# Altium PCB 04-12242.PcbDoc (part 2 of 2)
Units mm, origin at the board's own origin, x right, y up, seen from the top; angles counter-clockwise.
Board outline 90 x 78 mm, 2 copper layers (Top Layer, Bottom Layer), stack 1.57 mm thick; 64 components, 48 nets, 276 pads, 503 vias.
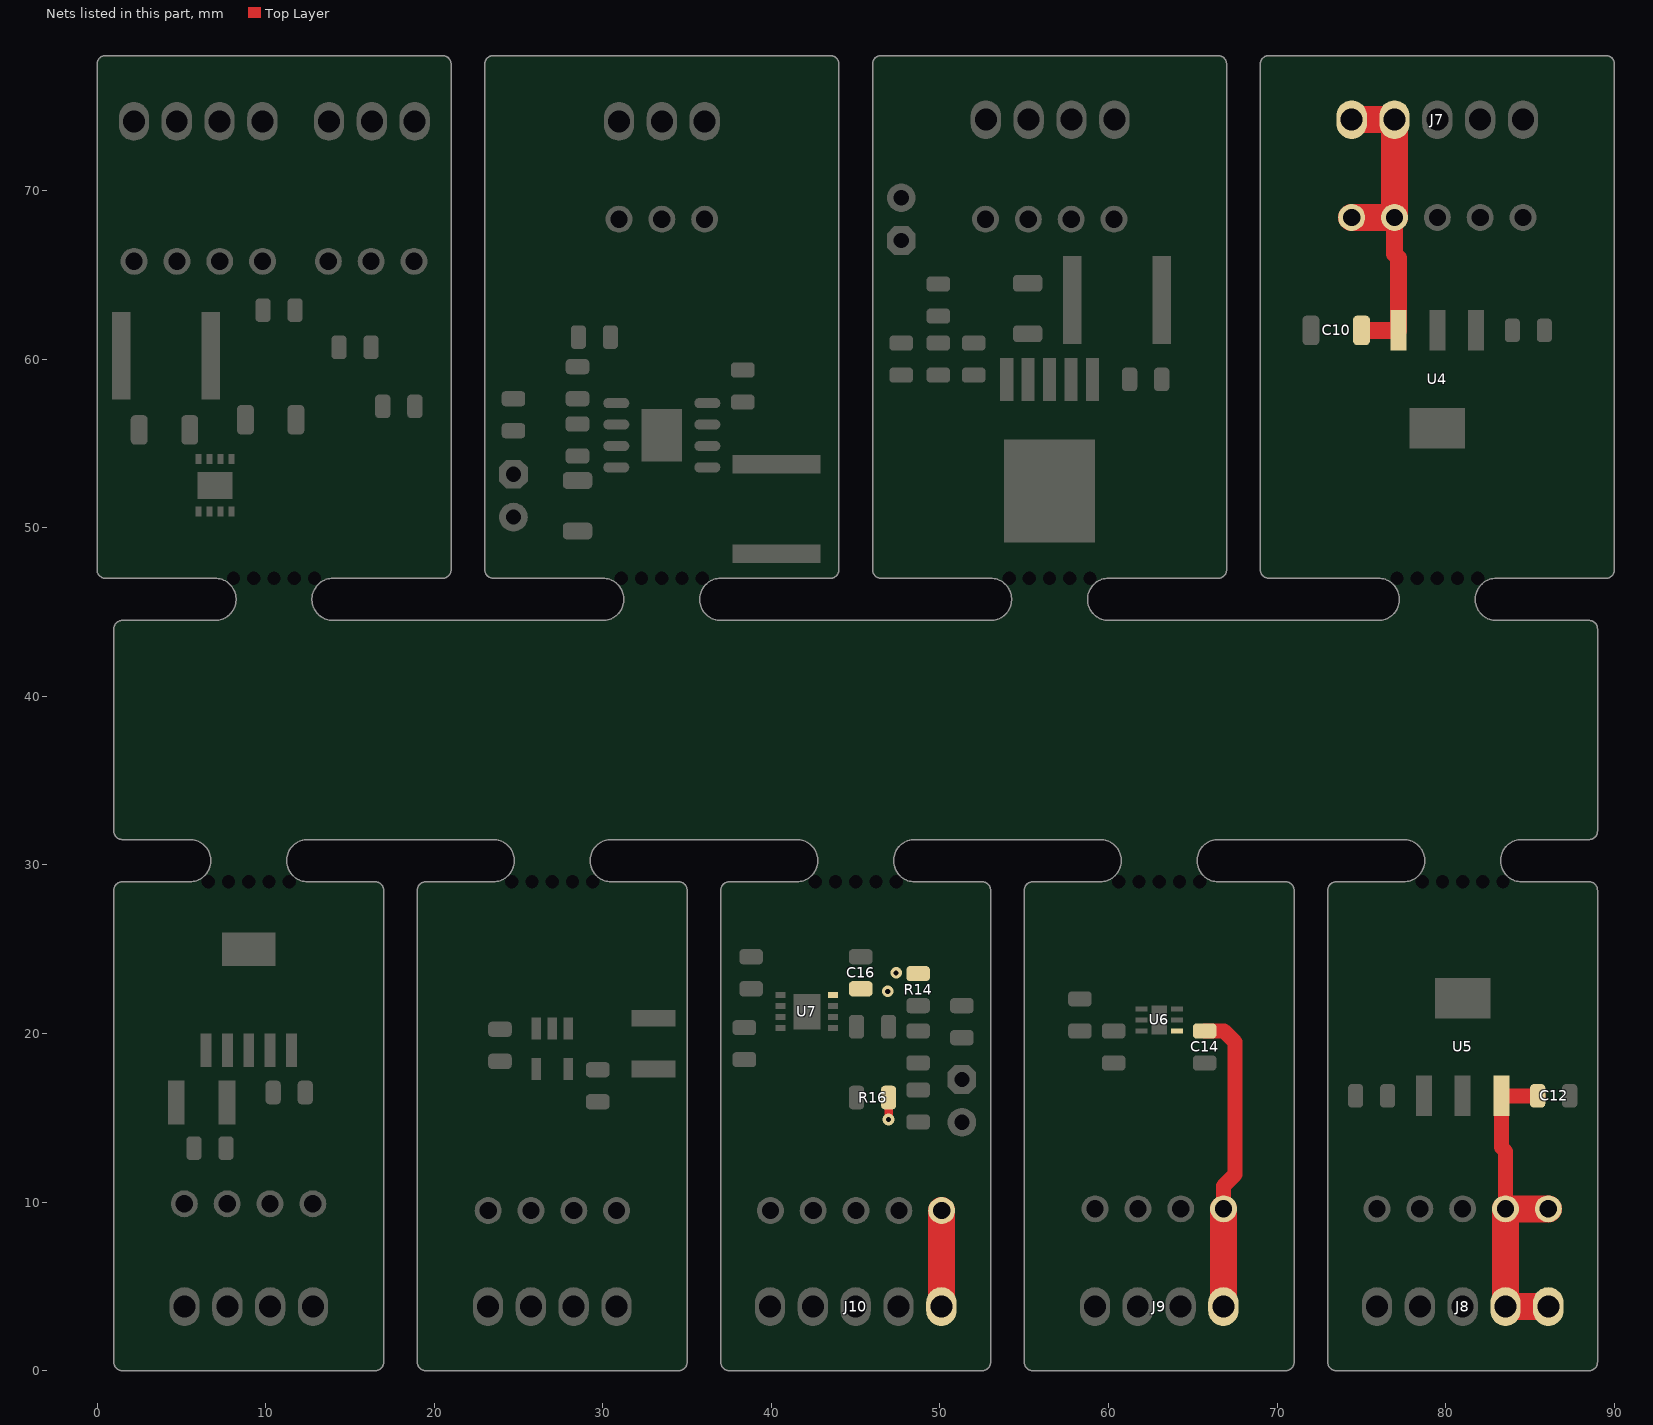
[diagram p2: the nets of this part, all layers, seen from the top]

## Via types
v1: diameter 0.7, hole 0.3, Top Layer to Bottom Layer, 503 vias

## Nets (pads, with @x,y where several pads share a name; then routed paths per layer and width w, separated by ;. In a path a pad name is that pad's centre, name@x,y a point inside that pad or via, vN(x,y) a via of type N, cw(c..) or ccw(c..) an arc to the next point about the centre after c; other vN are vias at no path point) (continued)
VOUT_6: C16.2 J10.5 pad.7@50.1,9.5 R14.2 R16.2 U7.8 | length 7
  Top Layer w0.5: v1(46.95,14.904) R16.2@46.95,16.2
  Top Layer w1.6: J10.5@50.08,3.8 50.1,3.82 pad.7@50.1,9.5
  other v1: 46.9,22.5 47.4,23.6
VOUT_7: C14.2 J9.4 pad.7@66.82,9.6 U6.4 | length 18.1
  Top Layer w0.9: C14.2@65.7,20.15 66.85,20.15 67.5,19.5 67.5,11.64 66.82,10.96 pad.7@66.82,9.6
  Top Layer w1.6: J9.4@66.81,3.8 66.81,9.59 pad.7@66.82,9.6
VOUT_8: C12.2 J8.4 J8.5 pad.7@83.54,9.6 pad.9@86.08,9.6 U5.3 | length 19.8
  Top Layer w0.9: pad.7@83.54,9.6 83.55,9.61 83.55,13 83.3,13.25 U5.3@83.3,16.3 C12.2@85.45,16.3
  Top Layer w1.6: J8.5@86.08,3.8 J8.4@83.54,3.8 pad.7@83.54,9.6 pad.9@86.08,9.6
VOUT_9: C10.2 J7.4 J7.5 pad.7@74.42,68.4 pad.7@76.96,68.4 U4.3 | length 19.9
  Top Layer w1: C10.2@75,61.7 U4.3@77.2,61.7 77.2,66 76.96,66.24 pad.7@76.96,68.4
  Top Layer w1.6: pad.7@74.42,68.4 pad.7@76.96,68.4 J7.4@76.96,74.2 J7.5@74.42,74.2
pads on no net: U1.6 U2.2 U2.3 U2.7 U6.5 U6.6 U8.4 U9.5

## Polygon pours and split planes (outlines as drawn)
VOUT1_1 on Top Layer "full" (solid, remove dead copper, pour order 49): 6.2,53.7 5.9,53.7 4.4,55.2 4.4,62 1.4,65 1.4,65.9 3,65.9 3,65.2 5.7,62.5 5.7,57.3 6.2,56.8
GND_9 on Top Layer "full" (solid, remove dead copper, pour order 102): 69.5,47.5 89.5,47.5 89.5,60 80.5,60 80.1,60.4 80.1,63.1 78.9,63.1 78.9,60.399 78.501,60 69.5,60
GND_8 on Top Layer "full" (solid, remove dead copper, pour order 103): 88.5,28.5 73.5,28.5 73.5,18 80,18 80.4,17.6 80.4,15 81.6,15 81.6,17.601 81.999,18 88.5,18
VOUT_5 on Top Layer "full" (solid, remove dead copper, pour order 41): 27.4,14 30.1,11.3 30.1,8.8 31.5,8.8 31.5,14.3 30.6,15.2 30.6,16.6 29.4,16.6 28.4,17.6 28.4,18.6 27.4,18.6 27.4,15.3
VOUT_3 on Top Layer "full" (solid, remove dead copper, pour order 98): 54.8,57.5 55.7,57.5 55.7,60.4 56.3,60.4 56.3,62.3 54.2,62.3 53.6,62.9 53.6,75.5 51.3,75.5 51.3,60.4 54.8,60.4
GND_3 on Top Layer "full" (solid, remove dead copper, pour order 96): 62.4,60.7 62.4,66.3 65.5,66.3 65.5,60.7
GND_1 on Top Layer "full" (solid, remove dead copper, pour order 94): 0.5,47.5 5.5,47.5 5.5,51.313 5.887,51.7 8.1,51.7 9.9,49.9 12.4,49.9 12.4,57.5 10.8,57.5 10.8,56 8.1,53.3 5.9,53.3 4,55.2 4,61.5 2.5,63 0.5,63 0.5,61.5
GND_2 on Top Layer "full" (solid, remove dead copper, pour order 60): 23.5,47.5 43.5,47.5 43.5,52.5 35.1,52.5 34.8,52.8 34.8,57.3 36,58.5 39.1,58.5 39.1,59.9 36.9,62.1 29.9,62.1 29.9,57 32.2,57 32.2,53 31,51.8 23.5,51.8
VOUT_2 on Top Layer "full" (solid, remove dead copper, pour order 57): 31.7,54.1 31.7,53.3 30.6,52.2 26.4,52.2 26.4,54.8 29.1,54.8 29.8,54.1
VIN_2 on Top Layer "full" (solid, remove dead copper, pour order 54): 35.3,54.2 35.3,52.9 43.5,52.9 43.5,62.1 36.9,68.7 35.1,68.7 35.1,65.5 39.5,61.1 39.5,56.6 37.1,54.2
ADJ_2 on Top Layer "full" (solid, remove dead copper, pour order 58): 31.7,56.6 31.7,55.6 27.7,55.6 27.7,58.2 29.3,58.2 29.3,57.2 29.9,56.6
GND_6 on Top Layer "full" (solid, remove dead copper, pour order 83): 40.1,16 44.2,16 44.2,18.4 42.9,19.7 42.9,22.5 44.3,23.9 46.2,23.9 47.3,25 52.5,25 52.5,28.5 37.5,28.5 37.5,23.9 39.9,23.9 41.3,22.5 41.3,20.6 40.1,20.6 40.1,18.4
VOUT_6 on Top Layer "full" (solid, remove dead copper, pour order 74): 43.3,22 43.3,22.5 44,23.2 44.1,23.3 46.3,23.3 47.2,24.2 49.6,24.2 49.6,22.9 48.2,22.9 47.3,22
NetC17_2 on Top Layer "full" (solid, remove dead copper, pour order 76): 43.3,21.2 45.6,21.2 45.6,19.6 44.7,19.6 44.5,19.8 44.5,20.5 44.3,20.7 43.3,20.7
VIN_6 on Top Layer "full" (solid, remove dead copper, pour order 73): 37.5,19.8 39.3,19.8 39.3,21.4 40.9,21.4 40.9,22.5 39.7,22.5 39.7,23.5 37.5,23.5
GND_7 on Top Layer "full" (solid, remove dead copper, pour order 69): 59.5,15 66.5,15 66.5,18.9 64.4,18.9 63.4,19.9 63.4,21.7 64.5,22.8 70.5,22.8 70.5,28.5 55.5,28.5 55.5,22.8 61.5,22.8 62.6,21.7 62.6,19.9 61.6,18.9 59.5,18.9
VOUT_7 on Top Layer "full" (solid, remove dead copper, pour order 67): 63.7,19.9 63.7,20.4 64.6,20.4 64.9,20.7 66.5,20.7 66.5,19.6 64.9,19.6 64.6,19.9
VIN_7 on Top Layer "full" (solid, remove dead copper, pour order 64): 62.3,20.4 62.3,19.9 61.4,19.9 61.1,19.6 57.5,19.6 57.5,20.7 61.1,20.7 61.4,20.4
VOUT2_1 on Top Layer "full" (solid, remove dead copper, pour order 53): 7.8,53.7 8.1,53.7 9.6,55.2 9.6,57.5 8.1,57.5 7.3,56.7 7.3,55 7.8,54.5
VIN_1 on Top Layer "full" (solid, remove dead copper, pour order 42): 6.9,53.7 6.5,53.7 6.5,56.913 6.1,57.313 6.1,62.9 7.4,62.9 7.4,57.413 6.9,56.913
GND_5 on Top Layer "full" (solid, remove dead copper, pour order 37): 30.6,21.5 31.7,20.4 34.5,20.4 34.5,28.5 19.5,28.5 19.5,21.5 26.5,21.5 26.7,21.3 26.7,19.6 27.3,19.6 27.3,21.3 27.5,21.5
VIN_5 on Top Layer "full" (solid, remove dead copper, pour order 30): 31.5,16 34.5,16 34.5,19.6 31.9,19.6 30.5,21 27.6,21 27.6,19.6 30.2,19.6 31.5,18.3
GND_4 on Top Layer "full" (solid, remove dead copper, pour order 27): 11.9,15.5 16.5,15.5 16.5,28.5 1.5,28.5 1.5,14.4 5.3,14.4 5.3,20.6 5.7,21 7.9,21 8.6,20.3 8.6,18 9.4,18 9.4,20.3 10.1,21 12,21 12.5,20.5 12.5,18 11.9,17.4
VOUT_4 on Top Layer "full" (solid, remove dead copper, pour order 23): 10.7,20 9.8,20 9.8,13.7 12,11.5 12,9.8 13.6,9.8 13.6,11.9 11,14.5 11,17.3 10.7,17.6
VIN_4 on Top Layer "full" (solid, remove dead copper, pour order 14): 8.1,20 7.3,20 7.3,17.6 6.9,17.2 6.9,9.8 8.5,9.8 8.5,17.2 8.1,17.6
GND_3 on Top Layer "full" (solid, remove dead copper, pour order 4): 46.5,56.8 66.5,56.8 66.5,47.5 46.5,47.5
VIN_3 on Top Layer "full" (solid, remove dead copper, pour order 13): 58.3,57.5 57.3,57.5 57.3,60.5 57,60.8 57,68.3 58.6,68.3 58.6,60.8 58.3,60.5
GND_1 on Bottom Layer "full" (solid, remove dead copper, pour order 12): 0.5,47.5 20.5,47.5 20.5,77.5 0.5,77.5
GND_8 on Bottom Layer "full" (solid, remove dead copper, pour order 79): 73.5,28.5 88.5,28.5 88.5,0.5 73.5,0.5
GND_9 on Bottom Layer "full" (solid, remove dead copper, pour order 35): 69.5,47.5 89.5,47.5 89.5,77.5 69.5,77.5
GND_5 on Bottom Layer "full" (solid, remove dead copper, pour order 51): 19.5,28.5 34.5,28.5 34.5,0.5 19.5,0.5
GND_2 on Bottom Layer "full" (solid, remove dead copper, pour order 81): 23.5,47.5 43.5,47.5 43.5,77.5 23.5,77.5
VIN_6 on Bottom Layer "full" (solid, remove dead copper, pour order 7): 45.8,9.4 44.2,9.4 44.2,10.5 37.5,17.2 37.5,22 39.5,22 39.5,17.3 45.8,11
VOUT_6 on Bottom Layer "full" (solid, remove dead copper, pour order 8): 46.4,13.9 49.3,11 49.3,9.5 50.9,9.5 50.9,11.4 47.9,14.4 47.9,24.1 46.4,24.1 46.4,15.8
GND_6 on Bottom Layer "full" (solid, remove dead copper, pour order 59): 37.5,28.5 52.5,28.5 52.5,0.5 37.5,0.5
GND_7 on Bottom Layer "full" (solid, remove dead copper, pour order 77): 55.5,28.5 70.5,28.5 70.5,0.5 55.5,0.5
VOUT_2 on Bottom Layer "full" (solid, remove dead copper, pour order 9): 28.3,52.2 26.4,52.2 26.4,59.1 30,62.7 30,69.3 31.9,69.3 31.9,62.1 28.3,58.5
VOUT2_1 on Bottom Layer "full" (solid, remove dead copper, pour order 6): 9.1,54.8 7.3,54.8 7.3,61.5 3.9,64.9 3.9,65.8 5.6,65.8 5.6,65 9.1,61.5
VIN_5 on Bottom Layer "full" (solid, remove dead copper, pour order 10): 26.5,8.8 25,8.8 25,10.2 31.8,17 34.5,17 34.5,15.5 32.5,15.5 26.5,9.5
GND_4 on Bottom Layer "full" (solid, remove dead copper, pour order 50): 1.5,28.5 16.5,28.5 16.5,0.5 1.5,0.5
GND_3 on Bottom Layer "full" (solid, remove dead copper, pour order 11): 46.5,47.5 66.5,47.5 66.5,77.5 46.5,77.5

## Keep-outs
Keep-Out Layer:
  text "'.Layer_Name'" at 297.5,-121.069 h1.5

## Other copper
Top Layer:
  text "'.ProjectPCBFabRevision'" at 332.678,-120.891 h1.5
  text "'.Layer_Name'" at 297.5,-121.069 h1.5
Bottom Layer:
  text "'.ProjectPCBFabNumber'-R'.ProjectPCBFabRevision'" at 2.5,32.673 h1 r270
  text ".ProjectPCBFabRevision" at 332.678,-120.891 h1.5
  text "'.Layer_Name'" at 297.5,-121.069 h1.5

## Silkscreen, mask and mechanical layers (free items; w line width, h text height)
Top Overlay:
  region: 19 vertices and 2 holes, not listed, extent 74.168,34.34 81.91,42.072
  text "VOUT" at 31.778,70.384 h1.2 r180
  text "GND" at 34.639,70.384 h1.2 r180
  text "VIN" at 37.05,70.384 h1.2 r180
  text "VOUT" at 53.678,70.284 h1.2 r180
  text "GND" at 56.439,70.284 h1.2 r180
  text "VIN" at 58.75,70.284 h1.2 r180
  text "EN" at 61.062,70.284 h1.2 r180
  text "VOUT" at 77.178,70.284 h1.2 r180
  text "GND" at 80.639,70.284 h1.2 r180
  text "VIN" at 84.15,70.284 h1.2 r180
  text "EN" at 14.244,68.038 h1.2 r90
  text "VIN" at 10.304,67.85 h1.2 r90
  text "GND" at 7.764,67.561 h1.2 r90
  text "PWG1" at 19.184,67.249 h1.2 r90
  text "PWG2" at 16.684,67.188 h1.2 r90
  text "VOUT1" at 2.584,66.97 h1.2 r90
  text "VOUT2" at 5.084,66.84 h1.2 r90
  text "'.ProjectPartNumber'" at 40.6,39.6 h2
  text "Building Block Solutions - Automotive LDOs" at 29.5,35.1 h2
  text "M" at 5,34 h8
  text "EN" at 4.438,7.716 h1.2
  text "VIN" at 6.75,7.716 h1.2
  text "GND" at 9.061,7.716 h1.2
  text "VOUT" at 11.822,7.716 h1.2
  text "EN" at 58.458,7.616 h1.2
  text "VIN" at 60.77,7.616 h1.2
  text "GND" at 63.081,7.616 h1.2
  text "VOUT" at 65.842,7.616 h1.2
  text "VIN" at 76.35,7.616 h1.2
  text "GND" at 79.761,7.616 h1.2
  text "VOUT" at 83.322,7.616 h1.2
  text "EN" at 22.458,7.516 h1.2
  text "VIN" at 24.77,7.516 h1.2
  text "GND" at 27.081,7.516 h1.2
  text "VOUT" at 29.842,7.516 h1.2
  text "PWG" at 38.632,7.516 h1.2
  text "EN" at 41.758,7.516 h1.2
  text "VIN" at 44.07,7.516 h1.2
  text "GND" at 46.381,7.516 h1.2
  text "VOUT" at 49.142,7.516 h1.2
  text "'.ProjectPCBFabRevision'" at 332.678,-120.891 h1.5
  text "'.Layer_Name'" at 297.5,-121.069 h1.5
Bottom Overlay:
  drawing of 9 lines, arcs and shapes, not listed
  text "Dual Output High Voltage LDO" at 2.263,72.054 h1.3 r180
  text "High Voltage LDO" at 28.6,72.054 h1.3 r180
  text "High Voltage LDO" at 51.6,72.054 h1.3 r180
  text "High Current LDO" at 74.52,72.054 h1.3 r180
  text "BBS1: MCP1722" at 5.463,70.435 h1.3 r180
  text "BBS2: MAQ5283" at 29,70.435 h1.3 r180
  text "BBS3: MCP1781" at 52.26,70.435 h1.3 r180
  text "BBS4: MCP1826S" at 74.6,70.435 h1.3 r180
  text "M" at 75.7,58 h4 r180
  text "M" at 52.9,57.8 h4 r180
  text "M" at 35.9,57.2 h4 r180
  text "M" at 12.8,52.2 h4 r180
  text "Vin: 13 - 24V  / Out1: 10V & 50mA / Out2: 3.3V & 50mA" at 4.3,44 h1.5 r180
  text "Vin: 6 - 100V / Out: 3V & 20mA" at 28.2,44 h1.5 r180
  text "Vin: 6 - 48V / Out: 5V & 80mA" at 51.9,44 h1.5 r180
  text "Vin: 5.5 - 6V / Out: 5V & 1A" at 75.7,44 h1.5 r180
  text "C" at 53,36.2 h8
  text "" at 22.4,35.9 h6
  text "1" at 36.4,35.9 h4
  text "4" at 44.7,35.5 h5
  text "Vin: 6.2 - 24V / Out: 5V & 100mA" at 13.7,32 h1.5
  text "Vin: 3.5 - 12V / Out: 1.8V & 50mA" at 31.6,32 h1.5
  text "Vin: 3.8 - 4.5V / Out: 3.3V & 1A" at 49.1,32 h1.5
  text "Vin: 3.5 - 5.5V / Out: 3.3V & 300mA" at 67.9,32 h1.5
  text "Vin: 2.1 - 5V / Out: 1.8V & 500mA" at 85.5,32 h1.5
  text "" at 28.9,31.949 h12.7
  text "M" at 46.7,20.1 h4
  text "M" at 84.7,20.1 h4
  text "M" at 63.13,19.5 h4
  text "M" at 28.143,17.243 h4
  text "M" at 9.3,17.1 h4
  text "BBS9: MCP1793" at 13.453,7.065 h1.3
  text "BBS8: MIC5233" at 31.321,7.065 h1.3
  text "BBS7: MCP1726" at 49.304,7.065 h1.3
  text "BBS6: MAQ5300" at 67.4,7.065 h1.3
  text "BBS5: MCP1825S" at 85.9,7.065 h1.3
  text "High Voltage LDO" at 13.9,5.446 h1.3
  text "High Voltage LDO" at 31.8,5.446 h1.3
  text "High Current LDO" at 49.8,5.446 h1.3
  text "Very Low Dropout Regulator" at 70.5,5.433 h1.24
  text "Low Voltage LDO" at 85.9,5.446 h1.3
  text "'.ProjectPCBFabRevision'" at 332.678,-120.891 h1.5
  text "'.Layer_Name'" at 297.5,-121.069 h1.5
Top Paste:
  text "'.ProjectPCBFabRevision'" at 332.678,-120.891 h1.5
  text "'.Layer_Name'" at 297.5,-121.069 h1.5
Bottom Paste:
  text "'.ProjectPCBFabRevision'" at 332.678,-120.891 h1.5
  text "'.Layer_Name'" at 297.5,-121.069 h1.5
Top Solder:
  text "'.ProjectPCBFabRevision'" at 332.678,-120.891 h1.5
  text "'.Layer_Name'" at 297.5,-121.069 h1.5
Bottom Solder:
  text "'.ProjectPCBFabRevision'" at 332.678,-120.891 h1.5
  text "'.Layer_Name'" at 297.5,-121.069 h1.5
NOTES (M1):
  text "'.Layer_Name'" at 315.5,-121.069 h1.5
BOARD (M2):
  lines w0.254: 1,0.496 1,28.5 cw(c1.5,28.5) 1.5,29 5.5,29 ccw(c5.5,30.25) 5.5,31.5 1.5,31.5 cw(c1.5,32) 1,32 1,44 cw(c1.5,44) 1.5,44.5 7,44.5 ccw(c7,45.75) 7,47 0.5,47 cw(c0.5,47.5) 0,47.5 0,77.5 cw(c0.5,77.5) 0.5,78 20.5,78 cw(c20.5,77.5) 21,77.5 21,47.5 cw(c20.5,47.5) 20.5,47 14,47 ccw(c14,45.75) 14,44.5 30,44.5 ccw(c30,45.75) 30,47 23.5,47 cw(c23.5,47.5) 23,47.5 23,77.5 cw(c23.5,77.5) 23.5,78 43.5,78 cw(c43.5,77.5) 44,77.5 44,47.5 cw(c43.5,47.5) 43.5,47 37,47 ccw(c37,45.75) 37,44.5 53,44.5 ccw(c53,45.75) 53,47 46.5,47 cw(c46.5,47.5) 46,47.5 46,77.5 cw(c46.5,77.5) 46.5,78 66.5,78 cw(c66.5,77.5) 67,77.5 67,47.5 cw(c66.5,47.5) 66.5,47 60,47 ccw(c60,45.75) 60,44.5 76,44.5 ccw(c76,45.75) 76,47 69.5,47 cw(c69.5,47.5) 69,47.5 69,77.5 cw(c69.5,77.5) 69.5,78 89.5,78 cw(c89.5,77.5) 90,77.5 90,47.5 cw(c89.5,47.5) 89.5,47 83,47 ccw(c83,45.75) 83,44.5 88.5,44.5 cw(c88.5,44) 89,44 89,32 cw(c88.5,32) 88.5,31.5 84.5,31.5 ccw(c84.5,30.25) 84.5,29 88.5,29 cw(c88.5,28.5) 89,28.5 89,0.495 ; 1,0.5 ccw(c1.5,0.5) 1.5,0 16.5,0 ccw(c16.5,0.5) 17,0.5 17,28.5 ccw(c16.5,28.5) 16.5,29 12.5,29 cw(c12.5,30.25) 12.5,31.5 23.5,31.5 cw(c23.5,30.25) 23.5,29 19.5,29 ccw(c19.5,28.5) 19,28.5 19,0.497 ; 19,0.5 ccw(c19.5,0.5) 19.5,0 34.5,0 ccw(c34.5,0.5) 35,0.5 35,28.5 ccw(c34.5,28.5) 34.5,29 30.5,29 cw(c30.5,30.25) 30.5,31.5 41.5,31.5 cw(c41.5,30.25) 41.5,29 37.5,29 ccw(c37.5,28.5) 37,28.5 37,0.5 ccw(c37.5,0.5) 37.5,0 52.5,0 ccw(c52.5,0.5) 53,0.5 53,28.5 ccw(c52.5,28.5) 52.5,29 48.5,29 cw(c48.5,30.25) 48.5,31.5 59.5,31.5 cw(c59.5,30.25) 59.5,29 55.5,29 ccw(c55.5,28.5) 55,28.5 55,0.5 ccw(c55.5,0.5) 55.5,0 70.5,0 ccw(c70.5,0.5) 71,0.5 ; 71,0.496 71,28.5 ccw(c70.5,28.5) 70.5,29 66.5,29 cw(c66.5,30.25) 66.5,31.5 77.5,31.5 cw(c77.5,30.25) 77.5,29 73.5,29 ccw(c73.5,28.5) 73,28.5 73,0.5 ccw(c73.5,0.5) 73.5,0 88.5,0 ccw(c88.5,0.5) 89,0.5
  text "'.ProjectPCBFabRevision'" at 332.678,-120.891 h1.5
  text "'.Layer_Name'" at 297.5,-121.069 h1.5
REF POINTS (M3):
  text "'.Layer_Name'" at 297.5,-121.069 h1.5
FAB (M4):
  lines w0.254: 326.624,73.583 328.148,73.583 ; 326.624,75.107 328.148,75.107 ; 327.386,74.345 327.386,75.869 ; 255.25,46.541 259.06,46.541 259.06,50.351 255.25,50.351 255.25,46.541 ; 255.25,52.151 255.25,55.961 259.06,55.961 259.06,52.151 255.25,52.151 ; 255.25,57.651 259.06,57.651 259.06,61.461 255.25,61.461 255.25,57.651 ; 255.25,62.931 255.25,66.741 259.06,66.741 259.06,62.931 255.25,62.931 ; 255.25,87.371 255.25,91.181 259.06,91.181 259.06,87.371 255.25,87.371 ; 255.75,20.431 259.56,20.431 259.56,24.241 255.75,24.241 255.75,20.431 ; 265.49,3.901 265.49,7.711 284.941,7.711 284.941,3.901 265.49,3.901 ; 275.441,15.755 275.441,19.565 335.441,19.565 335.441,15.755 275.441,15.755 ; 275.57,39.301 339.07,39.301 339.07,43.111 275.57,43.111 275.57,39.301 ; 283.19,87.371 287,87.371 287,91.181 283.19,91.181 283.19,87.371 ; 285.73,26.601 339.07,26.601 339.07,30.411 285.73,30.411 285.73,26.601 ; 285.73,32.951 285.73,36.761 339.07,36.761 339.07,32.951 285.73,32.951 ; 305.941,67.931 309.751,67.931 309.751,71.741 305.941,71.741 305.941,67.931 ; 306.05,72.821 314.94,72.821 314.94,76.631 306.05,76.631 306.05,72.821 ; 306.05,77.671 314.94,77.671 314.94,81.481 306.05,81.481 306.05,77.671 ; 306.05,82.521 306.05,86.331 314.94,86.331 314.94,82.521 306.05,82.521 ; 306.05,87.371 309.86,87.371 309.86,91.181 306.05,91.181 306.05,87.371 ; 314.78,3.901 331.941,3.901 331.941,7.711 314.78,7.711 314.78,3.901 ; 322.941,67.931 322.941,71.741 326.751,71.741 326.751,67.931 322.941,67.931 ; 328.91,72.821 328.91,76.631 337.8,76.631 337.8,72.821 328.91,72.821
  lines w0.3: 233.094,-53.819 243.242,-53.819 266.386,-53.819 287.78,-53.819 303.926,-53.819 318.072,-53.819 329.719,-53.819 ; 233.094,-50.819 243.242,-50.819 266.386,-50.819 287.78,-50.819 303.926,-50.819 318.072,-50.819 329.719,-50.819 ; 233.094,-47.819 243.242,-47.819 266.386,-47.819 287.78,-47.819 303.926,-47.819 318.072,-47.819 329.719,-47.819 ; 233.094,-44.819 243.242,-44.819 266.386,-44.819 287.78,-44.819 303.926,-44.819 318.072,-44.819 329.719,-44.819 ; 233.094,-41.819 243.242,-41.819 266.386,-41.819 287.78,-41.819 303.926,-41.819 318.072,-41.819 329.719,-41.819 ; 233.094,-38.819 243.242,-38.819 266.386,-38.819 287.78,-38.819 303.926,-38.819 318.072,-38.819 329.719,-38.819 ; 233.094,-35.819 329.719,-35.819 ; 243.242,-32.819 243.242,-56.819 ; 266.386,-32.819 266.386,-56.819 ; 287.78,-32.819 287.78,-56.819 ; 303.926,-32.819 303.926,-56.819 ; 318.072,-32.819 318.072,-56.819 ; 243.242,-56.819 233.094,-56.819 233.094,-32.819 329.719,-32.819 329.719,-56.819 318.072,-56.819 ; 243.242,-56.819 266.386,-56.819 ; 266.386,-56.819 287.78,-56.819 ; 287.78,-56.819 303.926,-56.819 ; 303.926,-56.819 318.072,-56.819
  text "THIS PCB TO BE MANUFACTURED TO MEET ALL ACCEPTANCE LEVELS" at 234.93,101.167 h1.78
  text "OF A CLASS 2 PCB PER ANSI/IPC-A-600G." at 234.93,97.357 h1.78
  text "MATERIAL:" at 234.93,92.737 h1.78
  text "FR-4 or Equivalent" at 255.25,92.737 h1.78
  text "CONTROLLED IMPEDANCE" at 311.441,88.505 h1.78
  text "MULTILAYER" at 260.965,88.387 h1.78
  text "2" at 284.46,88.387 h1.78
  text "LAYERS" at 288.905,88.387 h1.78
  text "Cu WEIGHT EXTERNAL LAYERS" at 255.25,83.537 h1.78
  text "35um" at 307.32,83.537 h1.78
  text "FINISHED" at 316.845,83.537 h1.78
  text "Cu WEIGHT INTERNAL LAYERS" at 255.25,78.687 h1.78
  text "N/A" at 307.32,78.687 h1.78
  text "FINISHED" at 316.845,78.687 h1.78
  text "FINISHED OVERALL THICKNESS" at 255.25,73.837 h1.78
  text "1.6" at 308.59,73.837 h1.78
  text "mm" at 316.845,73.837 h1.78
  text "10" at 331.45,73.837 h1.78
  text "%" at 339.705,73.837 h1.78
  text "COPPER THIEVING ALLOWED" at 255.441,69.005 h1.78
  text "YES" at 312.441,69.005 h1.78
  text "NO" at 329.441,69.005 h1.78
  text "X" at 324.032,68.505 h2.6
  text "FINISH:" at 234.941,64.505 h1.78
  text "LEAD-FREE HOT AIR LEVELING" at 260.941,64.205 h1.78
  text "X" at 256.341,63.505 h2.6
  text "IMMERSION GOLD" at 260.965,58.667 h1.78
  text "IMMERSION TIN" at 260.965,53.167 h1.78
  text "SMOBC WITH SELECTIVE GOLD PLATING ON LANDS" at 260.965,49.462 h1.78
  text "INDICATED. 1um GOLD OVER 5-10 um NICKEL" at 260.965,45.652 h1.78
  text "SOLDERMASK" at 255.25,40.317 h1.78
  text "DYNACHEM EPIC 200 LPI OR EQUIVALENT" at 276.84,40.317 h1.78
  text "SOLDERMASK COLOR" at 255.25,33.967 h1.78
  text "RED HIGH GLOSS" at 287,33.967 h1.78
  text "SILKSCREEN COLOR" at 255.25,27.617 h1.78
  text "WHITE" at 287,27.617 h1.78
  text "Blind / Burried Vias" at 261.441,21.505 h1.78
  text "DRILLING:" at 235.441,21.255 h1.78
  text "Via Layer Pairs" at 255.941,16.755 h1.78
  text "Top-Bottom" at 276.691,16.755 h1.78
  text "ALL HOLES TO BE LOCATED BY THE COORDINATES FROM THE NC DRILL DATA PROVIDED." at 234.93,11.505 h1.78
  text "'.ProjectPCBFabNumber'" at 266.941,5.005 h1.78
  text "PCB REV" at 302.941,5.005 h1.78
  text "USE ARTWORK SET NO." at 234.93,4.917 h1.78
  text "'.ProjectPCBFabRevision'" at 316.091,4.755 h1.78
  text "ALL UL LOGO, MANUFACTURER'S ID, AND DATE CODES SHALL BE PLACED" at 234.93,-1.433 h1.78
  text "ON THE BOTTOM SIDE UNLESS OTHERWISE INDICATED." at 234.93,-5.243 h1.78
  text "ANY ALTERNATIVES TO THE ABOVE SPECIFICATIONS MUST FIRST BE APPROVED." at 234.441,-10.495 h1.78
  text "Layer" at 234.794,-35.069 h1.5
  text "Name" at 244.942,-35.069 h1.5
  text "Material" at 268.086,-35.069 h1.5
  text "Thickness" at 289.48,-35.069 h1.5
  text "Constant" at 305.626,-35.069 h1.5
  text "Gerber" at 319.772,-35.069 h1.5
  text "Top Overlay" at 244.942,-38.069 h1.5
  text "GTO" at 319.772,-38.069 h1.5
  text "Top Solder" at 244.942,-41.069 h1.5
  text "Solder Resist" at 268.086,-41.069 h1.5
  text "0.010mm" at 289.48,-41.069 h1.5
  text "3.5" at 305.626,-41.069 h1.5
  text "GTS" at 319.772,-41.069 h1.5
  text "1" at 234.794,-44.069 h1.5
  text "Top Layer" at 244.942,-44.069 h1.5
  text "0.035mm" at 289.48,-44.069 h1.5
  text "GTL" at 319.772,-44.069 h1.5
  text "Dielectric1" at 244.942,-47.069 h1.5
  text "FR-4" at 268.086,-47.069 h1.5
  text "1.500mm" at 289.48,-47.069 h1.5
  text "4.8" at 305.626,-47.069 h1.5
  text "2" at 234.794,-50.069 h1.5
  text "Bottom Layer" at 244.942,-50.069 h1.5
  text "0.035mm" at 289.48,-50.069 h1.5
  text "GBL" at 319.772,-50.069 h1.5
  text "Bottom Solder" at 244.942,-53.069 h1.5
  text "Solder Resist" at 268.086,-53.069 h1.5
  text "0.010mm" at 289.48,-53.069 h1.5
  text "3.5" at 305.626,-53.069 h1.5
  text "GBS" at 319.772,-53.069 h1.5
  text "Bottom Overlay" at 244.942,-56.069 h1.5
  text "GBO" at 319.772,-56.069 h1.5
  text "Total board thickness:" at 234.794,-59.069 h1.5
  text "1.590mm" at 289.48,-59.069 h1.5
  text "'.ProjectPCBFabRevision'" at 332.678,-120.891 h1.5
  text "'.Layer_Name'" at 297.5,-121.069 h1.5
Case (M5):
  text "'.Layer_Name'" at 297.5,-121.069 h1.5
Cover (M6):
  text "'.Layer_Name'" at 297.5,-121.069 h1.5
Terminal Block (M7):
  text "'.Layer_Name'" at 297.5,-121.069 h1.5
Route Tool Path:
  text "'.Layer_Name'" at 297.5,-121.069 h1.5
V-Cut (M9):
  text "'.Layer_Name'" at 297.5,-121.069 h1.5
Bottom Assembly:
  text "'.VariantName'" at 47.07,-105.069 h0.9
  text "ASSEMBLY VARIANT:" at 61.32,-105.069 h0.9
  text "DOCUMENT NUMBER:" at 15.05,-113.319 h1.15
  text "'.ProjectPCBAssyNumber'_ASSY-D" at 15.177,-116.319 h1.4
  text "'.ProjectPCBAssyRevision'" at -1.878,-120.891 h1.5
  text "'.Layer_Name'" at 33,-121.069 h1
Top Assembly:
  text "ASSEMBLY NOTES:" at 26.4,-71.419 h4
  text "1. ALL COMPONENTS SHALL BE RoHS COMPLIANT." at -7.7,-76.519 h3
  text "2. ALL UNUSED THROUGH HOLE COMPONENT LOCATIONS SHALL BE FREE OF SOLDER." at -7.7,-79.519 h3
  text "3. ALL COMPONENTS SHALL BE MOUNTED FLUSH TO THE BOARD, EXCEPT AS NOTED." at -7.7,-82.519 h3
  text "4. FINISHED BOARD SHALL BE FREE OF ALL RESIDUES." at -7.7,-85.519 h3
  text "5. PLACE LABEL  ON THE LOCATION INDICATED." at -7.7,-88.519 h3
  text "6." at -7.7,-91.519 h3
  text "ASSEMBLY VARIANT:" at 269.5,-105.069 h0.9
  text "'.VariantName'" at 283.75,-105.069 h0.9
  text "DOCUMENT NUMBER:" at 315.75,-113.319 h1.15
  text "'.ProjectPCBAssyNumber'_ASSY-D" at 315.7,-116.319 h1.4
  text "'.ProjectPCBAssyRevision'" at 332.678,-120.891 h1.5
  text "'.Layer_Name'" at 297.5,-121.069 h1
Bottom 3D Body:
  text "'.Layer_Name'" at 297.5,-121.069 h1.15
Top 3D Body:
  text "'.Layer_Name'" at 297.5,-121.069 h1.2
Bottom Courtyard:
  text ".ProjectPCBFabRevision" at 332.678,-120.891 h1.5
  text "'.Layer_Name'" at 297.5,-121.069 h1
Top Courtyard:
  text "'.ProjectPCBFabRevision'" at 332.678,-120.891 h1.5
  text "'.Layer_Name'" at 297.5,-121.069 h1.1
TITLE (M16):
  lines w0.1: 269,-103.819 350.82,-103.819 ; 321,-96.319 321,-99.319 350.82,-99.319 ; 339.54,-120.954 339.54,-119.684 ; 339.54,-120.319 349.7,-120.319 ; 339.7,-119.119 339.7,-118.119 ; 339.7,-118.619 349.7,-118.619 ; 342.08,-120.954 342.08,-119.684 ; 344.62,-120.954 344.62,-119.684 ; 344.7,-118.919 344.7,-118.319 ; 347.16,-120.954 347.16,-119.684 ; 349.7,-120.954 349.7,-119.684 ; 349.7,-119.119 349.7,-118.119 ; 350.82,-99.319 350.82,-99.319
  lines w0.127: -25.1,-66.494 -20.02,-66.494 ; -25.1,-6.169 -20.02,-6.169 ; -25.1,54.156 -20.02,54.156 ; 38.4,-126.819 38.4,-121.739 ; 38.4,109.401 38.4,114.481 ; 101.9,-126.819 101.9,-121.739 ; 101.9,109.401 101.9,114.481 ; 165.4,-126.819 165.4,-121.739 ; 165.4,109.401 165.4,114.481 ; 200.96,-121.739 236.52,-121.739 ; 228.9,-126.819 228.9,-121.739 ; 228.9,109.401 228.9,114.481 ; 269,-121.739 269,-96.319 ; 269,-117.319 350.82,-117.319 ; 269,-111.319 350.82,-111.319 ; 269,-105.319 350.82,-105.319 ; 292.4,-126.819 292.4,-121.739 ; 292.4,109.401 292.4,114.481 ; 297,-121.739 297,-105.319 ; 315,-117.319 315,-111.319 ; 328,-121.739 328,-117.319 ; 335.5,-121.739 335.5,-111.319 ; 350.82,-91.259 350.82,-121.739 ; 350.82,-66.494 355.9,-66.494 ; 350.82,-6.169 355.9,-6.169 ; 350.82,54.156 355.9,54.156 ; 350.82,-121.739 350.82,-96.319 235,-96.319 235,-121.739 350.82,-121.739 ; 350.82,-121.739 -20.02,-121.739 -20.02,109.401 350.82,109.401 350.82,-121.739 ; -25.1,-126.819 355.9,-126.819 355.9,114.481 -25.1,114.481 -25.1,-126.819
  text "1" at 6.176,111.179 h1.78
  text "2" at 69.566,111.179 h1.78
  text "3" at 132.795,111.179 h1.78
  text "4" at 196.465,111.179 h1.78
  text "5" at 259.939,111.179 h1.78
  text "6" at 323.566,111.179 h1.78
  text "A" at -23.195,82.147 h1.78
  text "A" at 352.725,82.147 h1.78
  text "B" at -23.195,21.695 h1.78
  text "B" at 352.725,21.695 h1.78
  text "C" at -23.195,-38.63 h1.78
  text "C" at 352.725,-38.63 h1.78
  text "PART NUMBER:" at 322,-98.319 h1.15
  text "'.ProjectpartNumber'" at 334.5,-98.569 h1.5
  text "D" at -23.195,-98.828 h1.78
  text "TITLE:" at 270,-98.819 h1.15
  text "D" at 352.725,-98.828 h1.78
  text "'.ProjectTitle'" at 270,-102.819 h2.5
  text "PCB Layout Contact:" at 270,-107.319 h1.15
  text "PLOT NAME / GERBER FILE:" at 298,-107.319 h1.15
  text "'.ProjectContactPCB'" at 270,-110.319 h1.6
  text "'.Plot_File_Name'" at 298,-110.319 h1.5
  text "M" at 238,-112.319 h15.24
  text "Project Owner:" at 270,-113.319 h1.15
  text "PCB NUMBER:" at 298,-113.319 h1.15
  text "DATE:" at 336.7,-113.319 h1.15
  text "Microchip Technology Inc." at 236.77,-115.579 h1.78
  text "'.ProjectContactOwner'" at 270,-116.319 h1.6
  text "'.ProjectPCBFabNumber'" at 298,-116.319 h1.6
  text "'.PRINT_DATE'" at 336.7,-116.319 h1.5
  text "2355 W. Chandler Blvd." at 238,-118.319 h1.78
  text "LAYER NAME:" at 298,-118.819 h1.15
  text "10mm" at 336,-118.919 h0.7
  text "PCB FILE NAME:" at 270,-119.069 h1.15
  text "REV:" at 328.75,-119.069 h1.15
  text "400mil" at 335.9,-120.619 h0.7
  text "Chandler, AZ  85224" at 239,-120.819 h1.78
  text "'.PCB_FILE_NAME_NO_PATH'" at 270,-121.069 h1
  text "1" at 6.176,-125.041 h1.78
  text "2" at 69.566,-125.041 h1.78
  text "3" at 132.795,-125.041 h1.78
  text "4" at 196.465,-125.041 h1.78
  text "5" at 259.939,-125.041 h1.78
  text "6" at 323.566,-125.041 h1.78
Drill Drawing:
  circle w0.25: c-3.766,-25.136 r0.833
  lines w0.25: -4.6,-40.552 -4.183,-40.552 -3.766,-40.969 -3.35,-40.552 -2.933,-40.552 -3.35,-40.136 -2.933,-39.719 -3.35,-39.719 -3.766,-39.302 -4.183,-39.719 -4.6,-39.719 -4.183,-40.136 -4.6,-40.552 ; -4.6,-35.552 -2.933,-35.552 -3.766,-37.219 -4.6,-35.552 ; -4.6,-33.469 -3.766,-33.052 -2.933,-33.469 -3.35,-32.636 -2.933,-31.802 -3.766,-32.219 -4.6,-31.802 -4.183,-32.636 -4.6,-33.469 ; -4.6,-29.719 -2.933,-29.719 -2.933,-28.052 -4.6,-28.052 -4.6,-29.719
  lines w0.3: -6.095,-42.094 198.699,-42.094 ; -6.095,-23.344 198.699,-23.344 ; 7.677,-45.844 7.677,-19.594 ; 25.123,-45.844 25.123,-19.594 ; 58.763,-45.844 58.763,-19.594 ; 71.41,-45.844 71.41,-19.594 ; 108.898,-45.844 108.898,-19.594 ; 123.645,-45.844 123.645,-19.594 ; 141.99,-45.844 141.99,-19.594 ; 163.634,-45.844 163.634,-19.594 ; -6.095,-45.844 198.699,-45.844 198.699,-19.594 -6.095,-19.594 -6.095,-45.844
  text "Symbol" at -3.845,-22.219 h1.8
  text "Hit Count" at 8.802,-22.219 h1.8
  text "Finished Hole Size" at 26.248,-22.219 h1.8
  text "Plated" at 59.888,-22.219 h1.8
  text "Drill Layer Pair" at 72.535,-22.219 h1.8
  text "Via/Pad" at 110.023,-22.219 h1.8
  text "Hole Type" at 124.77,-22.219 h1.8
  text "Hole Length" at 143.115,-22.219 h1.8
  text "Routed Path Length" at 164.759,-22.219 h1.8
  text "6" at 8.802,-25.969 h1.5
  text "0.900mm (35.43mil)" at 26.248,-25.969 h1.5
  text "PTH" at 59.888,-25.969 h1.5
  text "Top Layer - Bottom Layer" at 72.535,-25.969 h1.5
  text "Pad" at 110.023,-25.969 h1.5
  text "Round" at 124.77,-25.969 h1.5
  text "-" at 143.115,-25.969 h1.5
  text "-" at 164.759,-25.969 h1.5
  text "41" at 8.802,-29.719 h1.5
  text "1.020mm (40.16mil)" at 26.248,-29.719 h1.5
  text "PTH" at 59.888,-29.719 h1.5
  text "Top Layer - Bottom Layer" at 72.535,-29.719 h1.5
  text "Pad" at 110.023,-29.719 h1.5
  text "Round" at 124.77,-29.719 h1.5
  text "-" at 143.115,-29.719 h1.5
  text "-" at 164.759,-29.719 h1.5
  text "41" at 8.802,-33.469 h1.5
  text "1.300mm (51.18mil)" at 26.248,-33.469 h1.5
  text "PTH" at 59.888,-33.469 h1.5
  text "Top Layer - Bottom Layer" at 72.535,-33.469 h1.5
  text "Pad" at 110.023,-33.469 h1.5
  text "Round" at 124.77,-33.469 h1.5
  text "-" at 143.115,-33.469 h1.5
  text "-" at 164.759,-33.469 h1.5
  text "45" at 8.802,-37.219 h1.5
  text "0.787mm (30.98mil)" at 26.248,-37.219 h1.5
  text "PTH" at 59.888,-37.219 h1.5
  text "Top Layer - Bottom Layer" at 72.535,-37.219 h1.5
  text "Pad" at 110.023,-37.219 h1.5
  text "Round" at 124.77,-37.219 h1.5
  text "-" at 143.115,-37.219 h1.5
  text "-" at 164.759,-37.219 h1.5
  text "503" at 8.802,-40.969 h1.5
  text "0.300mm (11.81mil)" at 26.248,-40.969 h1.5
  text "PTH" at 59.888,-40.969 h1.5
  text "Top Layer - Bottom Layer" at 72.535,-40.969 h1.5
  text "Via" at 110.023,-40.969 h1.5
  text "Round" at 124.77,-40.969 h1.5
  text "-" at 143.115,-40.969 h1.5
  text "-" at 164.759,-40.969 h1.5
  text "636 Total" at 8.802,-44.719 h1.5
  text "DOCUMENT NUMBER:" at 315.75,-113.319 h1.15
  text "'.ProjectPCBFabNumber'_FAB-D" at 315.7,-116.319 h1.4
  text "'.ProjectPCBFabRevision'" at 332.678,-120.891 h1.5
TITLE MIRROR (M17):
  lines w0.1: -18.9,-120.954 -18.9,-119.684 ; -18.9,-120.319 -8.74,-120.319 ; -18.9,-119.119 -18.9,-118.119 ; -18.9,-118.619 -8.9,-118.619 ; -16.36,-120.954 -16.36,-119.684 ; -13.9,-118.919 -13.9,-118.319 ; -13.82,-120.954 -13.82,-119.684 ; -11.28,-120.954 -11.28,-119.684 ; -8.9,-119.119 -8.9,-118.119 ; -8.74,-120.954 -8.74,-119.684
  lines w0.127: -25.1,-66.494 -20.02,-66.494 ; -25.1,-6.169 -20.02,-6.169 ; -25.1,54.156 -20.02,54.156 ; -20.02,-117.319 61.8,-117.319 ; -20.02,-111.319 61.8,-111.319 ; -20,-105.319 61.82,-105.319 ; -20,-103.819 61.82,-103.819 ; -20,-99.319 -19.383,-99.319 ; -4.7,-121.739 -4.7,-111.319 ; 2.8,-121.739 2.8,-117.319 ; 9.82,-96.319 9.82,-99.319 -19.383,-99.319 ; 15.8,-117.319 15.8,-111.319 ; 33.82,-121.739 33.82,-105.319 ; 38.4,-126.819 38.4,-121.739 ; 38.4,109.401 38.4,114.481 ; 61.82,-121.739 61.82,-96.319 ; 101.9,-126.819 101.9,-121.739 ; 101.9,109.401 101.9,114.481 ; 165.4,-126.819 165.4,-121.739 ; 165.4,109.401 165.4,114.481 ; 228.9,-126.819 228.9,-121.739 ; 228.9,109.401 228.9,114.481 ; 292.4,-126.819 292.4,-121.739 ; 292.4,109.401 292.4,114.481 ; 350.82,-66.494 355.9,-66.494 ; 350.82,-6.169 355.9,-6.169 ; 350.82,54.156 355.9,54.156 ; -20.02,-121.739 95.82,-121.739 95.82,-96.319 -20.02,-96.319 -20.02,-121.739 ; -20.02,-121.739 -20.02,109.401 350.82,109.401 350.82,-121.739 -20.02,-121.739 ; -19.383,-99.319 -19.383,-99.319 ; -25.1,-126.819 -25.1,114.481 355.9,114.481 355.9,-126.819 -25.1,-126.819
  text "6" at 7.234,111.179 h1.78
  text "5" at 70.861,111.179 h1.78
  text "4" at 134.336,111.179 h1.78
  text "3" at 198.005,111.179 h1.78
  text "2" at 261.234,111.179 h1.78
  text "1" at 324.624,111.179 h1.78
  text "A" at -21.925,82.147 h1.78
  text "A" at 353.995,82.147 h1.78
  text "B" at -21.925,21.695 h1.78
  text "B" at 353.995,21.695 h1.78
  text "C" at -21.925,-38.63 h1.78
  text "C" at 353.995,-38.63 h1.78
  text "PART NUMBER:" at 8.82,-98.319 h1.15
  text "'.ProjectpartNumber'" at -3.68,-98.569 h1.5
  text "D" at -21.925,-98.828 h1.78
  text "TITLE:" at 60.82,-98.819 h1.15
  text "D" at 353.995,-98.828 h1.78
  text "'.ProjectTitle'" at 60.82,-102.819 h2.5
  text "GERBER FILE:" at 32.82,-107.319 h1.15
  text "PCB Layout Contact:" at 60.82,-107.319 h1.15
  text "'.Plot_File_Name'" at 32.82,-110.319 h1.5
  text "'.ProjectContactPCB'" at 60.82,-110.319 h1.78
  text "M" at 92.82,-112.319 h15.24
  text "DATE:" at -5.9,-113.319 h1.15
  text "PCB NUMBER:" at 32.8,-113.319 h1.15
  text "Project Owner:" at 60.82,-113.319 h1.15
  text "Microchip Technology Inc." at 94.05,-115.579 h1.78
  text "'.PRINT_DATE'" at -5.9,-116.319 h1.5
  text "'.ProjectPCBFabNumber'" at 32.8,-116.319 h1.6
  text "'.ProjectContactOwner'" at 60.8,-116.319 h1.78
  text "2355 W. Chandler Blvd." at 92.82,-118.319 h1.78
  text "LAYER NAME:" at 32.8,-118.819 h1.15
  text "10mm" at -5.2,-118.919 h0.7
  text "REV:" at 2.05,-119.069 h1.15
  text "PCB FILE NAME:" at 60.8,-119.069 h1.15
  text "400mil" at -5.1,-120.619 h0.7
  text "Chandler, AZ  85224" at 91.82,-120.819 h1.78
  text "'.PCB_FILE_NAME_NO_PATH'" at 60.8,-121.069 h1
  text "6" at 7.234,-125.041 h1.78
  text "5" at 70.861,-125.041 h1.78
  text "4" at 134.336,-125.041 h1.78
  text "3" at 198.005,-125.041 h1.78
  text "2" at 261.234,-125.041 h1.78
  text "1" at 324.624,-125.041 h1.78

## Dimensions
73,0.5 to 89,0.495 on FAB (M4)
55,0.5 to 71,0.5 on FAB (M4)
37,0.5 to 53,0.5 on FAB (M4)
19,0.5 to 35,0.5 on FAB (M4)
1,0.5 to 17,0.5 on FAB (M4)
0.5,78 to 1.5,0 on FAB (M4)
1.5,44.5 to 1.5,31.5 on FAB (M4)
1.5,29 to 1.5,0 on FAB (M4)
90,77 to 0,47.5 on FAB (M4)
90,77.5 to 69,77.5 on FAB (M4)
67,77.5 to 46,77.5 on FAB (M4)
0.5,78 to 0.5,47 on FAB (M4)
44,77.5 to 23,77.5 on FAB (M4)
21,76.6 to 0,47.5 on FAB (M4)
